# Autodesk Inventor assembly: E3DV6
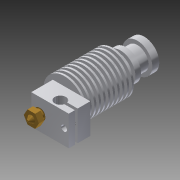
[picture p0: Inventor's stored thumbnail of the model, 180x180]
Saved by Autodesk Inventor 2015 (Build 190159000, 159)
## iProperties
Created: 2014-08
Part Number: E3DV6
Document SubType Name: Assembly
Designer: Jack
Author: Jack
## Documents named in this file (5)
- C:\Users\Jack\ownCloud\Projects\CoreXY\InventorModel\Extruder\E3DV6\E3DV6.iam
- C:\Users\Jack\ownCloud\Projects\CoreXY\InventorModel\Extruder\E3DV6\E3DV6HeatBreak.ipt
- C:\Users\Jack\ownCloud\Projects\CoreXY\InventorModel\Extruder\E3DV6\E3DV6HeatSink.ipt
- C:\Users\Jack\ownCloud\Projects\CoreXY\InventorModel\Extruder\E3DV6\E3DV6Nozzle.ipt
- C:\Users\Jack\ownCloud\Projects\CoreXY\InventorModel\Extruder\E3DV6\E3DV6NozzleBlock.ipt
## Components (4 placed, 4 different names)
1. E3DV6HeatBreak:1 — Mate:1, Mate:2, Mate:3, Mate:5
2. E3DV6HeatSink:1 — Mate:1, Mate:2
3. E3DV6Nozzle:1 — Mate:4, Mate:5, Flush:1
4. E3DV6NozzleBlock:1 — Mate:3, Mate:4, Flush:1
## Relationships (6: Mate 5, Flush 1)
- Mate:1: E3DV6HeatBreak:1 ↔ E3DV6HeatSink:1
- Mate:2: E3DV6HeatBreak:1 ↔ E3DV6HeatSink:1
- Mate:3: E3DV6HeatBreak:1 ↔ E3DV6NozzleBlock:1
- Mate:4: E3DV6Nozzle:1 ↔ E3DV6NozzleBlock:1
- Mate:5: E3DV6HeatBreak:1 ↔ E3DV6Nozzle:1
- Flush:1: E3DV6Nozzle:1 ↔ E3DV6NozzleBlock:1
